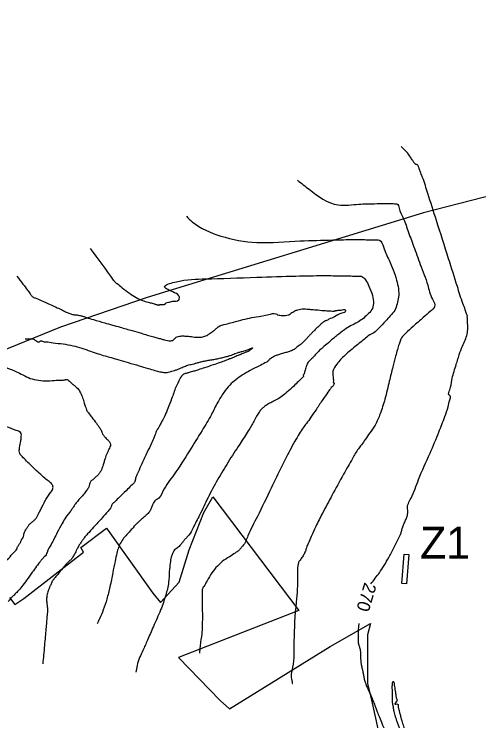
# Model space of a CAD drawing. Extents: x -478645 to -472650, y -1118147 to -1113892.
# Drawn here: x -476364.6 to -476219.3, y -1115572 to -1115351.1 of the extents above; entities that cross this region are included whole.
import ezdxf

# ---------------------------------------------------------------- set-up
doc = ezdxf.new("R2010")
doc.units = 0
for name, color, linetype in [('ObPÚ', 7, 'Continuous'), ('příčný žlab', 7, 'Continuous'), ('Vrstevnice_hlavni', 7, 'Continuous'), ('Vrstevnice_popis', 7, 'Continuous'), ('Vrstevnice_vedlejsi', 7, 'Continuous')]:
    doc.layers.add(name, color=color, linetype=linetype)

msp = doc.modelspace()

# ---------------------------------------------------------------- linework, layer by layer
at = {"layer": 'ObPÚ'}
for points in [[(-476052.59, -1115329.43), (-476039.45, -1115354.76), (-476078.43, -1115369.75), (-476116.95, -1115385.51), (-476155.82, -1115397.01), (-476158.12, -1115397.29), (-476191.74, -1115401.9), (-476214.85, -1115407.71), (-476217.94, -1115408.49), (-476236.62, -1115413.19), (-476323.01, -1115439.68), (-476350.14, -1115449), (-476375.02, -1115459.02)], [(-476366.06, -1115533.41), (-476364.38, -1115535.62), (-476361.53, -1115533.75), (-476342.91, -1115519.23), (-476343.77, -1115517.85), (-476335.69, -1115511.8), (-476321.19, -1115532.05), (-476318.87, -1115534.95), (-476312.96, -1115528.63), (-476309.84, -1115518.58), (-476305.27, -1115506.87), (-476302.45, -1115502.01), (-476275.63, -1115537.46), (-476313.19, -1115552.22), (-476300.19, -1115565.58), (-476297.23, -1115568.21), (-476265.79, -1115548.72), (-476253.16, -1115541.54), (-476254.16, -1115545.09), (-476254.09, -1115560.31), (-476252.89, -1115565.51), (-476247.06, -1115591.86)]]:
    msp.add_lwpolyline(points, dxfattribs=at)
at = {"layer": 'příčný žlab'}
for p, q in [((-476243.423, -1115529.04), (-476242.719, -1115519.916)), ((-476242.719, -1115519.916), (-476241.224, -1115520.031)), ((-476241.224, -1115520.031), (-476241.927, -1115529.155)), ((-476241.927, -1115529.155), (-476243.423, -1115529.04))]:
    msp.add_line(p, q, dxfattribs=at)
at = {"layer": 'Vrstevnice_hlavni'}
for points in [[(-476253.084, -1115529.163), (-476250.429, -1115525.695), (-476248.971, -1115523.469), (-476247.381, -1115520.75), (-476245.661, -1115517.539), (-476244.421, -1115515.046), (-476243.661, -1115513.27), (-476243.38, -1115512.212), (-476243, -1115511.084), (-476242.521, -1115509.887), (-476241.943, -1115508.619), (-476241.605, -1115507.501), (-476241.506, -1115506.533), (-476241.648, -1115505.715), (-476240.539, -1115502.403), (-476238.179, -1115496.598), (-476234.57, -1115488.299), (-476231.83, -1115481.739), (-476229.96, -1115476.919), (-476228.959, -1115473.839), (-476228.402, -1115471.685), (-476228.29, -1115470.458), (-476228.622, -1115470.157), (-476228.445, -1115468.5), (-476227.759, -1115465.489), (-476226.563, -1115461.122), (-476225.469, -1115457.584), (-476224.478, -1115454.874), (-476223.589, -1115452.994), (-476223.024, -1115451.121), (-476222.781, -1115449.256), (-476222.86, -1115447.397), (-476222.91, -1115446.152), (-476222.93, -1115445.519), (-476222.919, -1115445.5), (-476223.147, -1115444.832), (-476223.613, -1115443.518), (-476224.319, -1115441.555), (-476226.049, -1115436.252), (-476228.803, -1115427.608), (-476232.582, -1115415.623), (-476235.284, -1115407.156), (-476236.908, -1115402.206), (-476237.455, -1115400.774), (-476237.853, -1115399.704), (-476238.103, -1115398.997), (-476238.204, -1115398.651), (-476238.39, -1115398.385), (-476238.66, -1115398.199), (-476239.014, -1115398.092), (-476239.465, -1115397.662), (-476240.015, -1115396.91), (-476240.662, -1115395.834), (-476243.603, -1115392.555)], [(-476361.162, -1115452.581), (-476360.502, -1115452.594), (-476360.124, -1115452.6), (-476359.698, -1115452.605), (-476359.225, -1115452.61), (-476358.899, -1115452.609), (-476358.72, -1115452.601), (-476358.688, -1115452.587), (-476358.473, -1115452.713), (-476358.077, -1115452.978), (-476357.499, -1115453.383), (-476357.043, -1115453.576), (-476356.711, -1115453.558), (-476356.502, -1115453.327), (-476356.285, -1115453.216), (-476356.059, -1115453.223), (-476355.825, -1115453.35), (-476354.616, -1115453.553), (-476352.432, -1115453.833), (-476349.273, -1115454.189), (-476346.274, -1115454.744), (-476343.436, -1115455.496), (-476340.758, -1115456.445), (-476338.338, -1115457.257), (-476336.174, -1115457.932), (-476334.267, -1115458.468), (-476331.855, -1115459.164), (-476328.939, -1115460.019), (-476325.519, -1115461.034), (-476322.732, -1115461.848), (-476320.579, -1115462.463), (-476319.06, -1115462.877), (-476317.799, -1115463.096), (-476316.797, -1115463.12), (-476316.054, -1115462.948), (-476315.267, -1115462.732), (-476314.436, -1115462.471), (-476313.562, -1115462.166), (-476312.761, -1115461.86), (-476312.034, -1115461.555), (-476311.38, -1115461.249), (-476310.693, -1115460.985), (-476309.972, -1115460.764), (-476309.217, -1115460.585), (-476308.367, -1115460.371), (-476307.42, -1115460.122), (-476306.377, -1115459.838), (-476305.206, -1115459.571), (-476303.906, -1115459.322), (-476302.479, -1115459.089), (-476301.067, -1115458.819), (-476299.672, -1115458.512), (-476298.293, -1115458.167), (-476297.154, -1115457.84), (-476296.253, -1115457.53), (-476295.591, -1115457.237), (-476294.783, -1115456.948), (-476293.83, -1115456.665), (-476292.73, -1115456.386), (-476291.92, -1115456.156), (-476291.4, -1115455.977), (-476291.168, -1115455.846), (-476290.893, -1115455.713), (-476290.575, -1115455.576), (-476290.213, -1115455.436), (-476290.094, -1115455.451), (-476290.219, -1115455.622), (-476290.588, -1115455.948), (-476290.881, -1115456.193), (-476291.098, -1115456.355), (-476291.24, -1115456.434), (-476291.722, -1115456.646), (-476292.544, -1115456.989), (-476293.708, -1115457.465), (-476294.611, -1115457.835), (-476295.255, -1115458.098), (-476295.638, -1115458.254), (-476296.311, -1115458.524), (-476297.274, -1115458.906), (-476298.527, -1115459.402), (-476300.239, -1115460.023), (-476302.409, -1115460.771), (-476305.038, -1115461.644), (-476306.986, -1115462.279), (-476308.253, -1115462.673), (-476308.839, -1115462.829), (-476309.599, -1115463.049), (-476310.531, -1115463.335), (-476311.637, -1115463.685), (-476312.81, -1115465.138), (-476314.05, -1115467.692), (-476315.357, -1115471.347), (-476316.514, -1115474.339), (-476317.52, -1115476.668), (-476318.375, -1115478.334), (-476319.029, -1115479.573), (-476319.48, -1115480.384)], [(-476319.48, -1115480.384), (-476319.73, -1115480.767), (-476319.903, -1115481.026), (-476320.001, -1115481.161), (-476320.021, -1115481.171), (-476320.171, -1115481.534), (-476320.45, -1115482.25), (-476320.858, -1115483.32), (-476321.698, -1115485.239), (-476322.968, -1115488.009), (-476324.67, -1115491.629), (-476325.858, -1115494.253), (-476326.531, -1115495.88), (-476326.691, -1115496.512), (-476326.811, -1115496.978), (-476326.893, -1115497.278), (-476326.936, -1115497.412), (-476327.675, -1115498.193), (-476329.111, -1115499.62), (-476331.242, -1115501.694), (-476332.732, -1115503.122), (-476333.581, -1115503.906), (-476333.788, -1115504.045), (-476333.97, -1115504.293), (-476334.125, -1115504.65), (-476334.254, -1115505.116), (-476335.237, -1115506.413), (-476337.076, -1115508.542), (-476339.77, -1115511.502), (-476341.643, -1115513.593), (-476342.696, -1115514.814), (-476342.928, -1115515.166), (-476343.198, -1115515.552), (-476343.506, -1115515.972), (-476343.852, -1115516.425), (-476344.338, -1115517.23), (-476344.965, -1115518.387), (-476345.732, -1115519.896), (-476346.395, -1115521.011), (-476346.954, -1115521.731), (-476347.408, -1115522.058), (-476348.23, -1115522.913), (-476349.42, -1115524.297), (-476350.977, -1115526.21), (-476352.044, -1115527.527), (-476352.622, -1115528.246), (-476352.71, -1115528.37), (-476352.964, -1115528.932), (-476353.384, -1115529.933), (-476353.972, -1115531.373), (-476354.324, -1115532.77), (-476354.44, -1115534.122), (-476354.321, -1115535.431), (-476354.235, -1115536.39), (-476354.183, -1115536.999), (-476354.163, -1115537.259), (-476354.164, -1115537.592), (-476354.187, -1115537.998), (-476354.231, -1115538.478), (-476354.324, -1115539.511), (-476354.467, -1115541.098), (-476354.659, -1115543.237), (-476354.876, -1115545.675), (-476355.118, -1115548.411), (-476355.384, -1115551.445), (-476355.66, -1115554.158)], [(-476256.87, -1115541.558), (-476257.086, -1115545.423), (-476257.058, -1115547), (-476256.895, -1115548.222), (-476256.597, -1115549.088), (-476256.398, -1115550.068), (-476256.299, -1115551.162), (-476256.301, -1115552.369), (-476256.217, -1115553.527), (-476256.048, -1115554.637), (-476255.794, -1115555.698), (-476255.558, -1115556.771), (-476255.339, -1115557.856), (-476255.138, -1115558.953), (-476254.787, -1115560.149), (-476254.287, -1115561.445), (-476253.639, -1115562.84), (-476253.112, -1115564.012), (-476252.709, -1115564.959), (-476252.427, -1115565.681), (-476252.144, -1115566.412), (-476251.859, -1115567.15), (-476251.572, -1115567.896), (-476251.094, -1115569.116), (-476250.425, -1115570.809), (-476249.564, -1115572.975), (-476248.902, -1115574.544), (-476248.438, -1115575.515), (-476248.172, -1115575.889), (-476247.751, -1115576.483), (-476247.174, -1115577.298), (-476246.443, -1115578.333), (-476245.892, -1115579.078), (-476245.522, -1115579.532), (-476245.333, -1115579.697), (-476244.849, -1115579.952), (-476244.072, -1115580.298), (-476243, -1115580.735), (-476242.352, -1115580.648), (-476242.128, -1115580.039), (-476242.328, -1115578.906), (-476242.634, -1115577.786), (-476243.045, -1115576.677), (-476243.562, -1115575.579), (-476244.039, -1115574.478), (-476244.476, -1115573.373), (-476244.873, -1115572.265), (-476245.208, -1115571.242), (-476245.481, -1115570.304), (-476245.693, -1115569.452), (-476245.86, -1115568.728), (-476245.983, -1115568.132), (-476246.061, -1115567.665), (-476246.137, -1115567.212), (-476246.211, -1115566.773), (-476246.282, -1115566.348), (-476246.328, -1115565.71), (-476246.351, -1115564.858), (-476246.349, -1115563.793), (-476246.356, -1115562.911), (-476246.372, -1115562.211), (-476246.398, -1115561.694), (-476246.38, -1115561.111), (-476246.317, -1115560.463), (-476246.211, -1115559.748), (-476246.087, -1115559.558), (-476245.948, -1115559.892), (-476245.792, -1115560.751), (-476245.636, -1115561.677), (-476245.48, -1115562.669), (-476245.324, -1115563.728), (-476245.148, -1115564.759), (-476244.953, -1115565.761), (-476245.646, -1115566.754), (-476244.737, -1115566.736), (-476244.512, -1115567.722), (-476244.278, -1115568.717), (-476244.035, -1115569.723), (-476243.702, -1115570.947), (-476243.279, -1115572.39), (-476242.767, -1115574.05), (-476242.315, -1115575.51), (-476241.924, -1115576.769), (-476241.593, -1115577.826), (-476241.335, -1115578.617), (-476241.149, -1115579.141), (-476241.035, -1115579.398), (-476240.905, -1115579.707), (-476240.759, -1115580.07), (-476240.596, -1115580.485), (-476240.432, -1115580.885), (-476240.265, -1115581.271), (-476240.095, -1115581.641), (-476239.945, -1115581.98), (-476239.815, -1115582.29), (-476239.703, -1115582.568), (-476239.452, -1115583.138), (-476239.061, -1115583.998)]]:
    msp.add_spline(points, degree=3, dxfattribs=at)
at = {"layer": 'Vrstevnice_vedlejsi'}
for points in [[(-476276.009, -1115403.052), (-476272.404, -1115405.887), (-476263.315, -1115410.749), (-476256.811, -1115410.528), (-476251.961, -1115410.385), (-476248.767, -1115410.322), (-476247.227, -1115410.337), (-476246.084, -1115410.357), (-476245.34, -1115410.38), (-476244.993, -1115410.408), (-476244.244, -1115411.807), (-476243.092, -1115414.577), (-476241.537, -1115418.719), (-476239.726, -1115423.638), (-476237.657, -1115429.334), (-476235.33, -1115435.808), (-476233.832, -1115440.219), (-476233.162, -1115442.57), (-476233.319, -1115442.86), (-476234.496, -1115443.986), (-476236.692, -1115445.948), (-476239.907, -1115448.747), (-476242.171, -1115450.867), (-476243.483, -1115452.31), (-476243.845, -1115453.074), (-476244.279, -1115454.288), (-476244.785, -1115455.952), (-476245.364, -1115458.066), (-476246.211, -1115461.356), (-476247.327, -1115465.823), (-476248.712, -1115471.467), (-476250.19, -1115476.046), (-476251.763, -1115479.562), (-476253.43, -1115482.013), (-476254.856, -1115484.06), (-476256.039, -1115485.703), (-476256.981, -1115486.941), (-476258.835, -1115489.998), (-476261.601, -1115494.872), (-476265.281, -1115501.564), (-476268.191, -1115507.038), (-476270.334, -1115511.293), (-476271.708, -1115514.329), (-476272.671, -1115516.533), (-476273.224, -1115517.904), (-476273.367, -1115518.441), (-476273.565, -1115518.992), (-476273.819, -1115519.557), (-476274.129, -1115520.135), (-476274.466, -1115520.691), (-476274.831, -1115521.226), (-476275.223, -1115521.738), (-476275.502, -1115522.127), (-476275.667, -1115522.392), (-476275.718, -1115522.534), (-476275.979, -1115526.698), (-476276.45, -1115534.885), (-476277.131, -1115547.094), (-476277.576, -1115555.259), (-476277.786, -1115559.378), (-476277.76, -1115559.452), (-476277.743, -1115559.536), (-476277.735, -1115559.629), (-476277.735, -1115559.733), (-476277.728, -1115559.832), (-476277.713, -1115559.926), (-476277.692, -1115560.017), (-476277.671, -1115560.109), (-476277.653, -1115560.202), (-476277.635, -1115560.295), (-476277.627, -1115560.329)], [(-476310.764, -1115414.309), (-476308.919, -1115416.022), (-476300.01, -1115420.479), (-476288.754, -1115422.477), (-476275.153, -1115422.014), (-476265.012, -1115421.717), (-476258.332, -1115421.584), (-476255.112, -1115421.616), (-476252.723, -1115421.657), (-476251.167, -1115421.706), (-476250.441, -1115421.764), (-476249.178, -1115423.881), (-476247.375, -1115428.059), (-476245.034, -1115434.297), (-476244.437, -1115439.542), (-476245.585, -1115443.794)], [(-476340.832, -1115424.375), (-476333.591, -1115434.234), (-476333.353, -1115434.55), (-476332.431, -1115435.347), (-476330.824, -1115436.626), (-476328.532, -1115438.386), (-476326.42, -1115439.723), (-476324.488, -1115440.638), (-476322.737, -1115441.131), (-476321.476, -1115441.488), (-476320.705, -1115441.707)], [(-476363.771, -1115433.002), (-476361.824, -1115435.483), (-476360.478, -1115437.317), (-476359.554, -1115438.574), (-476359.053, -1115439.254), (-476358.975, -1115439.358), (-476357.995, -1115439.829), (-476356.115, -1115440.666), (-476353.333, -1115441.869), (-476351.103, -1115442.874), (-476349.425, -1115443.68), (-476348.298, -1115444.288), (-476347.182, -1115444.735), (-476346.075, -1115445.02), (-476344.979, -1115445.144), (-476343.938, -1115445.336), (-476342.954, -1115445.597), (-476342.024, -1115445.927), (-476339.802, -1115446.597), (-476336.287, -1115447.609), (-476331.48, -1115448.962), (-476327.658, -1115450.047), (-476324.822, -1115450.863), (-476322.972, -1115451.412), (-476321.329, -1115451.89), (-476319.894, -1115452.296), (-476318.667, -1115452.631), (-476317.589, -1115452.899), (-476316.66, -1115453.101), (-476315.881, -1115453.236), (-476315.249, -1115453.177), (-476314.764, -1115452.922), (-476314.427, -1115452.472), (-476313.932, -1115452.125), (-476313.279, -1115451.881), (-476312.47, -1115451.74), (-476311.268, -1115451.729), (-476309.676, -1115451.848)], [(-476320.705, -1115441.707), (-476320.425, -1115441.79), (-476320.176, -1115441.863), (-476319.958, -1115441.924), (-476319.773, -1115441.975), (-476319.609, -1115442.016), (-476319.469, -1115442.046), (-476319.351, -1115442.067), (-476319.255, -1115442.058), (-476319.182, -1115442.019), (-476319.13, -1115441.951), (-476319.055, -1115441.898), (-476318.957, -1115441.862), (-476318.834, -1115441.84), (-476318.652, -1115441.839), (-476318.411, -1115441.856), (-476318.11, -1115441.894), (-476317.855, -1115441.885), (-476317.646, -1115441.83), (-476317.481, -1115441.728), (-476317.33, -1115441.624), (-476317.193, -1115441.517), (-476317.07, -1115441.408), (-476316.356, -1115441.197), (-476315.05, -1115440.885), (-476313.155, -1115440.471), (-476312.946, -1115439.57), (-476314.424, -1115438.181), (-476317.59, -1115436.304), (-476314.371, -1115434.872), (-476304.769, -1115433.884), (-476288.783, -1115433.341), (-476276.493, -1115432.995), (-476267.897, -1115432.846), (-476262.997, -1115432.896), (-476259.362, -1115432.958), (-476256.993, -1115433.032), (-476255.889, -1115433.12), (-476254.786, -1115434.158), (-476253.683, -1115436.146), (-476252.58, -1115439.085), (-476252.299, -1115441.557), (-476252.839, -1115443.56), (-476254.202, -1115445.096), (-476255.717, -1115446.417), (-476257.386, -1115447.525), (-476259.209, -1115448.418), (-476261.31, -1115449.764), (-476263.69, -1115451.562), (-476266.349, -1115453.813), (-476268.248, -1115455.442), (-476269.385, -1115456.45), (-476269.761, -1115456.838), (-476270.218, -1115457.325), (-476270.755, -1115457.911), (-476271.373, -1115458.597), (-476271.874, -1115459.114), (-476272.256, -1115459.462), (-476272.522, -1115459.641), (-476272.86, -1115460.244), (-476273.273, -1115461.273), (-476273.759, -1115462.726), (-476274.064, -1115463.711), (-476274.188, -1115464.227), (-476274.131, -1115464.276), (-476274.17, -1115464.391), (-476274.304, -1115464.572), (-476274.535, -1115464.82), (-476275.369, -1115465.624), (-476276.806, -1115466.984), (-476278.846, -1115468.9), (-476280.736, -1115470.439), (-476282.477, -1115471.602), (-476284.069, -1115472.387), (-476285.391, -1115473.138), (-476286.445, -1115473.857), (-476287.229, -1115474.542), (-476288.024, -1115475.529), (-476288.83, -1115476.818), (-476289.647, -1115478.409), (-476291.4, -1115481.326), (-476294.09, -1115485.57), (-476297.716, -1115491.141), (-476301.018, -1115496.691), (-476303.994, -1115502.221), (-476306.646, -1115507.731), (-476308.656, -1115511.659), (-476310.025, -1115514.007), (-476310.753, -1115514.775), (-476311.407, -1115515.511), (-476311.987, -1115516.217), (-476312.493, -1115516.893), (-476313.02, -1115517.463), (-476313.569, -1115517.929), (-476314.14, -1115518.291), (-476314.649, -1115518.897), (-476315.099, -1115519.747)], [(-476309.676, -1115451.848), (-476307.692, -1115452.096), (-476306.008, -1115452.038), (-476304.623, -1115451.673), (-476303.538, -1115451.003), (-476302.543, -1115450.315), (-476301.638, -1115449.609), (-476300.823, -1115448.887), (-476298.43, -1115448.001), (-476294.461, -1115446.953), (-476288.914, -1115445.743), (-476285.027, -1115445.026), (-476282.8, -1115444.803), (-476282.232, -1115445.074), (-476281.534, -1115445.246), (-476280.707, -1115445.318), (-476279.749, -1115445.29), (-476278.989, -1115445.157), (-476278.426, -1115444.921), (-476278.061, -1115444.579), (-476277.528, -1115444.233), (-476276.828, -1115443.882), (-476275.961, -1115443.526), (-476275.043, -1115443.315), (-476274.072, -1115443.248), (-476273.049, -1115443.325), (-476271.568, -1115443.441), (-476269.628, -1115443.596), (-476267.23, -1115443.791), (-476265.57, -1115443.907), (-476264.649, -1115443.946), (-476264.466, -1115443.907), (-476264.283, -1115443.862), (-476264.101, -1115443.811), (-476263.918, -1115443.753), (-476263.354, -1115443.691), (-476262.407, -1115443.625), (-476261.077, -1115443.553), (-476260.984, -1115443.877), (-476262.126, -1115444.596), (-476264.504, -1115445.711), (-476266.192, -1115446.499), (-476267.191, -1115446.962), (-476267.5, -1115447.098), (-476267.969, -1115447.43), (-476268.598, -1115447.957), (-476269.387, -1115448.68), (-476269.927, -1115449.176), (-476270.22, -1115449.446), (-476270.264, -1115449.489), (-476270.511, -1115449.737), (-476270.962, -1115450.192), (-476271.615, -1115450.853), (-476272.302, -1115451.574), (-476273.024, -1115452.354), (-476273.78, -1115453.193), (-476274.488, -1115453.891), (-476275.149, -1115454.446), (-476275.762, -1115454.859), (-476276.181, -1115455.166), (-476276.406, -1115455.368), (-476276.438, -1115455.464), (-476276.662, -1115455.638), (-476277.078, -1115455.89), (-476277.686, -1115456.22), (-476278.56, -1115456.567), (-476279.701, -1115456.929), (-476281.108, -1115457.307), (-476282.27, -1115457.678), (-476283.188, -1115458.042), (-476283.86, -1115458.398), (-476284.406, -1115458.755), (-476284.826, -1115459.112), (-476285.12, -1115459.469), (-476286.208, -1115460.147), (-476288.09, -1115461.146), (-476290.765, -1115462.466), (-476293.17, -1115463.888), (-476295.303, -1115465.413), (-476297.166, -1115467.039), (-476299.054, -1115469.383), (-476300.968, -1115472.444), (-476302.907, -1115476.222), (-476305.84, -1115481.259), (-476309.766, -1115487.555), (-476314.684, -1115495.111), (-476318.099, -1115500.213), (-476320.012, -1115502.86), (-476320.422, -1115503.054), (-476320.824, -1115503.523), (-476321.22, -1115504.267), (-476321.609, -1115505.286), (-476321.951, -1115506.066), (-476322.247, -1115506.607), (-476322.496, -1115506.909), (-476323, -1115507.409), (-476323.758, -1115508.106)], [(-476245.585, -1115443.794), (-476248.476, -1115447.053), (-476250.673, -1115449.358), (-476252.176, -1115450.709), (-476252.985, -1115451.105), (-476254.769, -1115452.423), (-476257.527, -1115454.662), (-476261.262, -1115457.823), (-476263.735, -1115460.519), (-476264.949, -1115462.751), (-476264.902, -1115464.519), (-476264.818, -1115465.742), (-476264.697, -1115466.42), (-476264.538, -1115466.553), (-476264.613, -1115466.837), (-476264.922, -1115467.269), (-476265.463, -1115467.852), (-476266.511, -1115469.268), (-476268.064, -1115471.518), (-476270.123, -1115474.603), (-476271.839, -1115477.11), (-476273.212, -1115479.042), (-476274.242, -1115480.397), (-476275.454, -1115482.256), (-476276.848, -1115484.618), (-476278.424, -1115487.485), (-476280.902, -1115492.361), (-476284.281, -1115499.247), (-476288.562, -1115508.142), (-476291.522, -1115514.184), (-476293.162, -1115517.373), (-476293.481, -1115517.709), (-476293.767, -1115518.032), (-476294.022, -1115518.342), (-476294.243, -1115518.638), (-476295.149, -1115519.315), (-476296.738, -1115520.374), (-476299.011, -1115521.813), (-476301.027, -1115523.603), (-476302.785, -1115525.744), (-476304.286, -1115528.234), (-476305.295, -1115529.995), (-476305.814, -1115531.026), (-476305.841, -1115531.326), (-476305.841, -1115532.836), (-476305.813, -1115535.555), (-476305.758, -1115539.483), (-476305.833, -1115542.836), (-476306.04, -1115545.616), (-476306.377, -1115547.821), (-476306.579, -1115549.632), (-476306.641, -1115550.847)], [(-476375.392, -1115462), (-476374.129, -1115461.473), (-476373.218, -1115461.118), (-476372.659, -1115460.933), (-476372.45, -1115460.919), (-476372.087, -1115460.802), (-476371.568, -1115460.58), (-476370.895, -1115460.255), (-476370.204, -1115460.181), (-476369.496, -1115460.36), (-476368.77, -1115460.791), (-476367.914, -1115461.219), (-476366.926, -1115461.642), (-476365.807, -1115462.062), (-476364.304, -1115462.716), (-476362.417, -1115463.605), (-476360.145, -1115464.728), (-476357.641, -1115465.438), (-476354.904, -1115465.734), (-476351.935, -1115465.618), (-476349.849, -1115465.502), (-476348.647, -1115465.387), (-476348.329, -1115465.272), (-476347.968, -1115465.34), (-476347.565, -1115465.59), (-476347.119, -1115466.023), (-476346.516, -1115466.573), (-476345.755, -1115467.242), (-476344.837, -1115468.03), (-476344.033, -1115469.141), (-476343.343, -1115470.576), (-476342.768, -1115472.335), (-476342.342, -1115473.633), (-476342.065, -1115474.468), (-476341.938, -1115474.841), (-476341.36, -1115475.721), (-476340.333, -1115477.106), (-476338.856, -1115478.997), (-476337.825, -1115480.446), (-476337.242, -1115481.454), (-476337.106, -1115482.02), (-476336.708, -1115482.699), (-476336.047, -1115483.489), (-476335.123, -1115484.392), (-476334.613, -1115485.234), (-476334.515, -1115486.014), (-476334.83, -1115486.732), (-476335.165, -1115487.505), (-476335.519, -1115488.332), (-476335.893, -1115489.212), (-476336.181, -1115489.954), (-476336.384, -1115490.556), (-476336.5, -1115491.018), (-476336.678, -1115491.638), (-476336.918, -1115492.417), (-476337.22, -1115493.354), (-476337.658, -1115494.21), (-476338.234, -1115494.984), (-476338.946, -1115495.678), (-476339.549, -1115496.226), (-476340.042, -1115496.627), (-476340.425, -1115496.883), (-476340.759, -1115497.34), (-476341.045, -1115497.997), (-476341.282, -1115498.856), (-476341.828, -1115499.854), (-476342.682, -1115500.993), (-476343.846, -1115502.272), (-476344.811, -1115503.411), (-476345.578, -1115504.411), (-476346.146, -1115505.272), (-476346.807, -1115506.216), (-476347.56, -1115507.242), (-476348.405, -1115508.352), (-476349.595, -1115510.321), (-476351.128, -1115513.152), (-476353.005, -1115516.842), (-476354.314, -1115519.344), (-476355.055, -1115520.656), (-476355.227, -1115520.78), (-476355.538, -1115521.104), (-476355.989, -1115521.629), (-476356.58, -1115522.354), (-476357.559, -1115523.662), (-476358.927, -1115525.554), (-476360.684, -1115528.028), (-476362.218, -1115530.038), (-476363.528, -1115531.584), (-476364.614, -1115532.666), (-476365.375, -1115533.438), (-476365.811, -1115533.898), (-476365.922, -1115534.047), (-476366.035, -1115534.195), (-476366.151, -1115534.34), (-476366.269, -1115534.483), (-476366.37, -1115534.607), (-476366.453, -1115534.711)], [(-476386.868, -1115563.77), (-476386.404, -1115558.49), (-476385.983, -1115553.73), (-476385.843, -1115552.17), (-476384.718, -1115549.256), (-476382.607, -1115544.988), (-476379.51, -1115539.367), (-476377.347, -1115535.488), (-476376.117, -1115533.352), (-476375.821, -1115532.959), (-476375.527, -1115532.539), (-476375.236, -1115532.091), (-476374.948, -1115531.616), (-476374.711, -1115531.173), (-476374.526, -1115530.763), (-476374.393, -1115530.385), (-476374.22, -1115530.026), (-476374.008, -1115529.686), (-476373.756, -1115529.365), (-476373.437, -1115528.968), (-476373.052, -1115528.496), (-476372.6, -1115527.948), (-476372.158, -1115527.393), (-476371.726, -1115526.831), (-476371.304, -1115526.261), (-476370.255, -1115525.116), (-476368.58, -1115523.398), (-476366.278, -1115521.105), (-476364.681, -1115519.417), (-476363.788, -1115518.333), (-476363.599, -1115517.854), (-476363.38, -1115517.403), (-476363.131, -1115516.981), (-476362.852, -1115516.586), (-476362.624, -1115516.208), (-476362.447, -1115515.848), (-476362.32, -1115515.506), (-476362.183, -1115515.228), (-476362.036, -1115515.015), (-476361.879, -1115514.866), (-476361.743, -1115514.589), (-476361.628, -1115514.182), (-476361.535, -1115513.647), (-476361.302, -1115513.008), (-476360.931, -1115512.265), (-476360.421, -1115511.418), (-476359.844, -1115510.674), (-476359.201, -1115510.032), (-476358.493, -1115509.493), (-476357.886, -1115508.861), (-476357.381, -1115508.138), (-476356.978, -1115507.323), (-476356.457, -1115506.284), (-476355.818, -1115505.02), (-476355.061, -1115503.532), (-476354.274, -1115502.169), (-476353.457, -1115500.932), (-476352.611, -1115499.821), (-476352.458, -1115498.76), (-476353, -1115497.749), (-476354.236, -1115496.789), (-476355.796, -1115495.443), (-476357.679, -1115493.713), (-476359.885, -1115491.598), (-476361.477, -1115490.015), (-476362.455, -1115488.962), (-476362.82, -1115488.441), (-476362.968, -1115487.633), (-476362.899, -1115486.539), (-476362.614, -1115485.158), (-476362.433, -1115483.976), (-476362.356, -1115482.993), (-476362.383, -1115482.21), (-476363.943, -1115481.232), (-476367.039, -1115480.058), (-476371.668, -1115478.69), (-476374.855, -1115477.913), (-476376.599, -1115477.729), (-476376.9, -1115478.137), (-476377.722, -1115478.533), (-476379.064, -1115478.919), (-476380.926, -1115479.294), (-476382.829, -1115479.558), (-476384.771, -1115479.713), (-476386.754, -1115479.758), (-476388.635, -1115479.895), (-476390.415, -1115480.123)], [(-476323.758, -1115508.106), (-476324.771, -1115509.001), (-476325.591, -1115509.738), (-476326.218, -1115510.318), (-476326.652, -1115510.741), (-476326.953, -1115511.029), (-476327.119, -1115511.185), (-476327.152, -1115511.207), (-476327.181, -1115511.246), (-476327.205, -1115511.302), (-476327.225, -1115511.375), (-476327.711, -1115511.943), (-476328.662, -1115513.005), (-476330.077, -1115514.561), (-476331.18, -1115516.169), (-476331.97, -1115517.829), (-476332.447, -1115519.541), (-476333.052, -1115522.155), (-476333.785, -1115525.67), (-476334.647, -1115530.087), (-476335.628, -1115533.965), (-476336.729, -1115537.305), (-476337.95, -1115540.108), (-476338.621, -1115541.646)], [(-476315.099, -1115519.747), (-476315.487, -1115520.841), (-476315.818, -1115522.698), (-476316.092, -1115525.318), (-476316.307, -1115528.701), (-476317.21, -1115532.699), (-476318.801, -1115537.313), (-476321.08, -1115542.543), (-476322.934, -1115546.773), (-476324.363, -1115550.003), (-476325.367, -1115552.233), (-476326.154, -1115554.694), (-476326.597, -1115556.734)]]:
    msp.add_spline(points, degree=3, dxfattribs=at)

# ---------------------------------------------------------------- texts
at = {"layer": 'příčný žlab'}
msp.add_text('Z1', height=10, rotation=359.99999, dxfattribs=at).set_placement((-476237.702, -1115521.302))
at = {"layer": 'Vrstevnice_popis'}
msp.add_text(' 270 ', height=4, rotation=253.13001, dxfattribs=at).set_placement((-476254.628, -1115527.104))

doc.saveas('drawing.dxf')
